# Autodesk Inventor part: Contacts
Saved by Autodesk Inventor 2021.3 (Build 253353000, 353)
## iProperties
Created: 2023-03
Part Number: Contacts
Material: Generic
Document SubType Name: Modeling
Designer: AdminForWorker
Density: 1 g/cm^3
Appearance: Default
Title: Contacts
Author: AdminForWorker
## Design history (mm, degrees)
feature "Body1"
body "Solid1"
